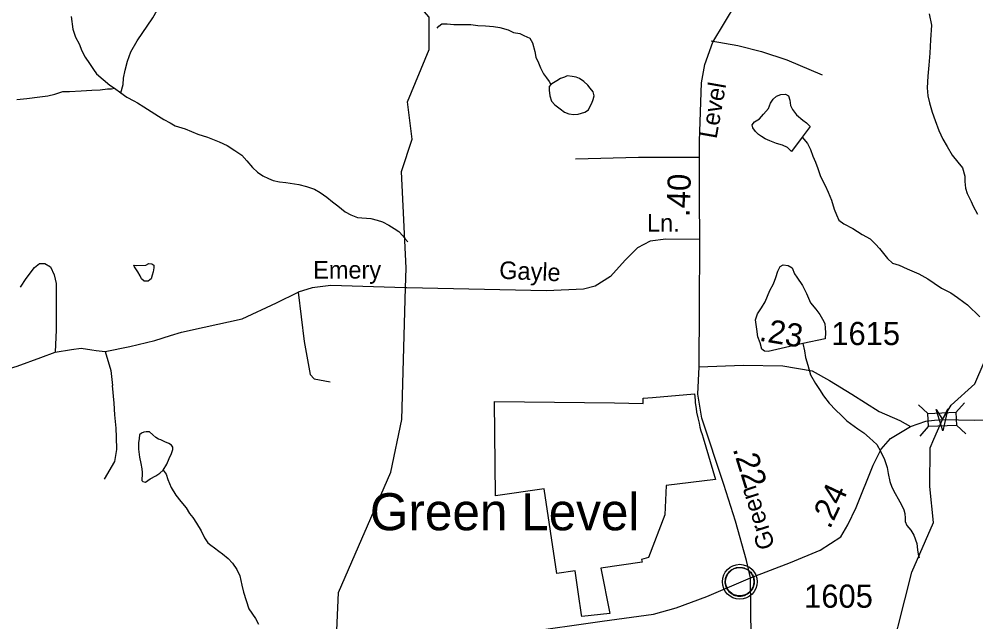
# Model space of a CAD drawing. Extents: x 2001466 to 2224147, y 644118 to 847247.
# Drawn here: x 2024898 to 2030071, y 738177 to 741433 of the extents above; entities that cross this region are included whole.
import ezdxf

# ---------------------------------------------------------------- set-up
doc = ezdxf.new("R2010")
doc.units = 0
for name, color, linetype in [('Exist Boundary Political City Limit New', 7, 'Continuous'), ('Exist Civil Demographics Community CELL', 7, 'Continuous'), ('Exist Civil Demographics Community Label', 7, 'Continuous'), ('Exist Hydrographic Creek Single Shore', 7, 'Continuous'), ('Exist Hydrographic Misc Water Feature', 7, 'Continuous'), ('Exist Road Non-System Type 51', 7, 'Continuous'), ('Exist Road Non-System Type 51 Label', 7, 'Continuous'), ('Exist Road Secondary Mileage Hundredths English Label', 7, 'Continuous'), ('Exist Road Secondary Structure Standard Bridge Attributed CELL', 7, 'Continuous'), ('Exist Road Secondary Structure Standard Bridge CELL', 7, 'Continuous'), ('Exist Road Secondary Type 51 Attributed', 7, 'Continuous'), ('Exist Road Secondary Type 51 Label', 7, 'Continuous'), ('Exist Road Secondary Type 51 Number Label', 7, 'Continuous'), ('Map Preparation Boundary City Limit Buffer Line', 7, 'Continuous')]:
    doc.layers.add(name, color=color, linetype=linetype)

msp = doc.modelspace()

# ---------------------------------------------------------------- linework, layer by layer
at = {"layer": 'Exist Boundary Political City Limit New'}
msp.add_lwpolyline([(2028553.9, 739360.9), (2028557.9, 739330.2), (2028561, 739309.8), (2028566.9, 739279.4), (2028573.8, 739249.7), (2028578.8, 739229.8), (2028584.4, 739209.9), (2028590.5, 739190.2), (2028596.8, 739172.1), (2028663.5, 738946.8), (2028395.5, 738914.3), (2028389, 738754.8), (2028301.2, 738525.5), (2028263.5, 738513.7), (2028266.4, 738499.6), (2028043.5, 738468.2), (2028092.4, 738223.1), (2027940.5, 738205.8), (2027939.1, 738214.6), (2027922, 738327.6), (2027903.6, 738453), (2027805.6, 738438.4), (2027737.4, 738896.3), (2027472.8, 738857.9), (2027467.5, 739367.9), (2028117.5, 739360.3), (2028272, 739356.4), (2028271.6, 739385.7), (2028322.4, 739389.6), (2028550, 739409.6), (2028552.5, 739375.4), (2028553.9, 739360.9)], dxfattribs=at)
at = {"layer": 'Exist Civil Demographics Community CELL'}
msp.add_lwpolyline([(2028716.7, 738406.4), (2028717.7, 738411.9), (2028719.5, 738418.5), (2028722.4, 738425.7), (2028725.3, 738431.5), (2028728.7, 738437.2), (2028732.4, 738442.3), (2028736.4, 738446.7), (2028741, 738451.3), (2028746.5, 738455.9), (2028751.9, 738459.5), (2028756.8, 738462.4), (2028761.9, 738464.8), (2028767.3, 738467.1), (2028773, 738469), (2028777.3, 738470.1), (2028782.1, 738470.8), (2028786.3, 738471.6), (2028792.6, 738471.8), (2028797.1, 738471.7), (2028802.7, 738471.5), (2028807.6, 738470.7), (2028812.5, 738469.8), (2028817.5, 738468.3), (2028822.7, 738466.4), (2028829.4, 738463.5), (2028835.6, 738460), (2028840.7, 738456.4), (2028845.9, 738452.4), (2028849.2, 738449.3), (2028853.3, 738444.9), (2028857.2, 738440.2), (2028860.2, 738435.6), (2028863.4, 738430.6), (2028865.8, 738425.5), (2028867.8, 738420.4), (2028869.4, 738415.4), (2028870.7, 738410.8), (2028871.8, 738404.8), (2028872.4, 738400.1), (2028872.7, 738394.1), (2028872.5, 738388.3), (2028871.9, 738382.6), (2028871, 738377.1), (2028869.3, 738371), (2028867.5, 738365.1), (2028865.2, 738360.1), (2028862, 738354.1), (2028858.7, 738348.7), (2028855.3, 738344.1), (2028851, 738339.3), (2028845.8, 738334.3), (2028840.7, 738330.2), (2028835.7, 738326.8), (2028831.4, 738324.3), (2028824.6, 738321), (2028817.4, 738318.3), (2028811.5, 738316.9), (2028804.9, 738315.6), (2028800.5, 738315.1), (2028796, 738314.8), (2028790.4, 738314.8), (2028786.1, 738315.2), (2028780.5, 738316), (2028774.6, 738317.3), (2028770, 738318.6), (2028764.8, 738320.5), (2028760.2, 738322.4), (2028756.3, 738324.7), (2028749.5, 738328.8), (2028743.9, 738333), (2028739, 738337.5), (2028734.5, 738342.4), (2028731.4, 738346.3), (2028728.4, 738350.5), (2028724.3, 738357.6), (2028722.6, 738361.2), (2028720.8, 738365.2), (2028718.3, 738373.4), (2028716.7, 738380.4), (2028716, 738385.6), (2028715.7, 738391.9), (2028715.6, 738396.6), (2028716.2, 738403.1)], close=True, dxfattribs=at)
for centre, radius in [((2028794.3, 738393.9), 94.3), ((2028794.1, 738394.2), 76.7)]:
    msp.add_circle(centre, radius, dxfattribs=at)
at = {"layer": 'Exist Hydrographic Creek Single Shore'}
for points in [[(2026987.2, 739982.2), (2026990.3, 740087.1), (2026965.3, 740609.4), (2027023.3, 740785.4), (2026998.3, 740986), (2027114.3, 741269.1), (2027114.3, 741443), (2027048.3, 741519.8), (2027048.3, 741647.4)], [(2026442.4, 736836.9), (2026442.4, 736951.8), (2026525.2, 737153.5), (2026567.3, 737359.4), (2026575.3, 737634.8), (2026600.3, 737762.3), (2026625.3, 738336), (2026908.3, 738986.4), (2026966.3, 739270.6), (2026987.2, 739982.2)], [(2029041.2, 737319.5), (2029076.3, 737355.3), (2029333.2, 737512.9), (2029575.4, 737855.7), (2029724.2, 738446.5), (2029841.3, 738713.3), (2029821.2, 738907.8), (2029822.7, 739116.8), (2029843.6, 739163.8), (2029889.8, 739269.7), (2029936.8, 739347.3), (2030065.2, 739463.3), (2030165.3, 739697.5)]]:
    msp.add_lwpolyline(points, dxfattribs=at)
at = {"layer": 'Exist Hydrographic Misc Water Feature'}
msp.add_line((2025413, 741059.4), (2025448.9, 741034.9), dxfattribs=at)
for points in [[(2025448.9, 741034.9), (2025459.8, 741079.7), (2025463.3, 741114.2), (2025471.1, 741157.5), (2025484.8, 741205.6), (2025502.4, 741256.1), (2025535.9, 741316.1), (2025567.4, 741360.5), (2025591.2, 741394.5), (2025621.2, 741440.7), (2025644.5, 741481.1), (2025664.4, 741516.8), (2025678.4, 741537.1), (2025695.6, 741563.8)], [(2025178.9, 741448), (2025189.3, 741378.1), (2025203.5, 741336), (2025221.9, 741300.3), (2025236.3, 741262.4), (2025254.5, 741226.7), (2025278.5, 741192.5), (2025300.9, 741160.9), (2025317.3, 741136.8), (2025389.4, 741077.1), (2025413, 741059.4)], [(2029818, 741461.6), (2029830.5, 741399.8), (2029824.9, 741322), (2029821.6, 741249.9), (2029816.1, 741183.6), (2029810.6, 741125.4), (2029806.9, 741061.6), (2029811.2, 741018), (2029819.6, 740980.1), (2029833.7, 740929.7), (2029849.9, 740885.9), (2029870.4, 740832.2), (2029892.8, 740784.2), (2029915.4, 740744.3), (2029941.6, 740698.7), (2029974, 740661.1), (2029998, 740629.4), (2030010.5, 740584.9), (2030010.7, 740555.3), (2030014.8, 740519.2), (2030023.2, 740491.1), (2030045.4, 740447.2), (2030055.8, 740423.2), (2030079.8, 740379.3)], [(2027158, 741384.1), (2027167.2, 741395.1), (2027183.2, 741407.1), (2027213, 741407.3), (2027249.1, 741403.3), (2027275.1, 741403.6), (2027313, 741403.6), (2027341.1, 741403.9), (2027377.2, 741398.3), (2027419.5, 741396.6), (2027463.1, 741394), (2027497.4, 741388.4), (2027541.3, 741374.4), (2027571.4, 741360.6), (2027605.4, 741355), (2027627.6, 741344.7), (2027659.6, 741329.3), (2027673.7, 741305.3), (2027685.8, 741257.4), (2027692, 741226.9), (2027706.1, 741197.2), (2027716.2, 741169), (2027732.4, 741137.5), (2027748.6, 741115.1), (2027764.6, 741095.9), (2027773.4, 741080.1)], [(2027773.4, 741080.1), (2027764.6, 741069.7), (2027764.6, 741049.9), (2027766.8, 741019.5), (2027776.9, 740989.7), (2027795.1, 740969.7), (2027823, 740947.8), (2027847.2, 740930.1), (2027869.3, 740922.3), (2027897.2, 740917.6), (2027921, 740920.4), (2027957.1, 740930.3), (2027977.2, 740942.2), (2027985.2, 740962.6), (2027995, 740978.8), (2028000.8, 740998.3), (2028006.7, 741018.7), (2028001, 741040.2), (2027984.6, 741060.2), (2027972.7, 741076), (2027950.5, 741096.2), (2027928.6, 741112.2), (2027910.4, 741119.9), (2027888.4, 741123.7), (2027860.5, 741125.9), (2027846.4, 741119.6), (2027824.2, 741111.9), (2027804.5, 741100), (2027786.5, 741088), (2027773.4, 741080.1)], [(2024886, 740999.6), (2024940, 741004.2), (2025009.9, 741012.7), (2025054, 741019.2), (2025091.9, 741027.4), (2025133.7, 741041.3), (2025169.6, 741041.4), (2025233.8, 741045.8), (2025291.8, 741048.7), (2025335.7, 741051.1), (2025375.7, 741056.8), (2025397.6, 741057.2), (2025413, 741059.4)], [(2025448.9, 741034.9), (2025479.9, 741012.1), (2025518.2, 740992.4), (2025538.5, 740980.5), (2025572.6, 740958.5), (2025650.9, 740909.4), (2025681, 740891.5), (2025715.3, 740873.5), (2025741.5, 740857.4), (2025795.2, 740839.9), (2025863.7, 740812.3), (2025915.8, 740794.8), (2025980.2, 740769.7), (2026022.2, 740750), (2026064.3, 740723.7), (2026102.6, 740698.3), (2026128.9, 740668.2), (2026159, 740632.3), (2026187.1, 740607.2), (2026215.6, 740586.9), (2026245.5, 740571.5), (2026271.6, 740561.2), (2026305.6, 740553.9), (2026339.7, 740549.9), (2026409.8, 740540.3), (2026452, 740528.8), (2026494.3, 740514.8), (2026526.3, 740497), (2026562.3, 740471.6), (2026592.5, 740445.5), (2026620.6, 740423.6), (2026660.8, 740392.4), (2026691.1, 740376.2), (2026727.2, 740360.7), (2026799.4, 740355.2), (2026833.4, 740347.1), (2026863.4, 740337.4), (2026897.6, 740319.5), (2026925.9, 740301.7), (2026951.7, 740286.4), (2026971.8, 740262.3), (2026984.1, 740248.1), (2027000.3, 740229.7)], [(2029132.3, 740794.8), (2029074.4, 740717.2), (2029052.3, 740739), (2029026, 740752.7), (2028992, 740760.7), (2028956.1, 740776.2), (2028932.1, 740786.6), (2028911.8, 740798.5), (2028895.8, 740810.3), (2028879.8, 740826.2), (2028865.7, 740846.2), (2028861.6, 740861.8), (2028873.7, 740878), (2028901.6, 740894.6), (2028923.3, 740920.5), (2028949.4, 740950.3), (2028961.2, 740978.7), (2028975, 741000.6), (2028993.2, 741016.7), (2029017, 741025.2), (2029041, 741027.2), (2029057.2, 741018.6), (2029065.2, 740994.7), (2029069.1, 740966.7), (2029079.2, 740945.1), (2029101.5, 740916.8), (2029135.3, 740887.4), (2029155.6, 740873), (2029175.5, 740853.8), (2029132.3, 740794.8)], [(2029132.3, 740794.8), (2029161, 740761.4), (2029177.2, 740729), (2029189.3, 740693.5), (2029203.6, 740659.6), (2029215.7, 740625.7), (2029230.1, 740583.6), (2029256.5, 740533.9), (2029272.9, 740498.2), (2029291, 740454.4), (2029305.3, 740406.5), (2029317.8, 740376.7), (2029329.9, 740346.2), (2029356.2, 740326.7), (2029406.2, 740302.8), (2029456.4, 740268.9), (2029498.9, 740245.9), (2029528.8, 740217.4), (2029549.3, 740194), (2029571.5, 740166.5), (2029593.6, 740140.6), (2029619.9, 740114.7), (2029655.8, 740104.9), (2029700, 740085.1), (2029762.2, 740057.6), (2029810.4, 740029.5), (2029844.6, 740005.9), (2029884.6, 739980.5), (2029935, 739954.8), (2029971.1, 739928.7), (2030005.4, 739905), (2030025.5, 739889), (2030091.9, 739825.3)], [(2025595.1, 740018.1), (2025590.4, 740018.1), (2025574.4, 740017.6), (2025560.3, 740030.3), (2025552.1, 740046), (2025540.4, 740067.5), (2025521.9, 740095.8), (2025518, 740104.1), (2025532.2, 740102.2), (2025584, 740104.4), (2025600, 740112.2), (2025616, 740111.9), (2025626.1, 740104.4), (2025626.1, 740090.3), (2025622, 740068.3), (2025618.3, 740050.3), (2025612.3, 740030), (2025604.3, 740024.4), (2025595.1, 740018.1)], [(2029134.9, 739680), (2028948.3, 739637.8), (2028928.4, 739639.9), (2028914.3, 739650), (2028904.4, 739683.9), (2028891.9, 739716.1), (2028886, 739758), (2028879.8, 739808.2), (2028889.7, 739841.7), (2028911.6, 739874.1), (2028931.5, 739906.4), (2028956.9, 739966.6), (2028976.8, 740003.9), (2028988.9, 740036.5), (2029000.8, 740072.3), (2029012.7, 740096.7), (2029028.7, 740106.2), (2029056.6, 740102.3), (2029076.7, 740088.8), (2029090.8, 740056.5), (2029102.9, 740039.1), (2029133.1, 739995), (2029155.2, 739951.1), (2029177.4, 739901.4), (2029205.7, 739865.5), (2029227.8, 739837.2), (2029242, 739813.2), (2029253.9, 739789.1), (2029256.1, 739763.6), (2029258.2, 739739.8), (2029256.3, 739707), (2029134.9, 739680)], [(2029134.9, 739680), (2029145, 739641.2), (2029149.1, 739605), (2029161.6, 739563), (2029175.9, 739511), (2029204.4, 739465.3), (2029224.7, 739432.1), (2029246.9, 739398), (2029277, 739358), (2029313.3, 739320.4), (2029341.6, 739294.4), (2029373.8, 739262.5), (2029432.3, 739219.5), (2029464.4, 739197.5), (2029496.4, 739171.4), (2029534.8, 739136.2), (2029555.1, 739099.7), (2029577.4, 739054.1), (2029591.8, 739012), (2029596.1, 738978.2), (2029606.3, 738936.2), (2029616.6, 738904.8), (2029634.8, 738870.8), (2029651, 738841), (2029669.1, 738808.6), (2029681.6, 738782.9), (2029685.7, 738763.2), (2029688, 738736.9), (2029688, 738718.8), (2029698.2, 738697.3), (2029718.5, 738673.1), (2029734.5, 738644.9), (2029750.7, 738601), (2029755.2, 738567.3), (2029759.3, 738543.4), (2029764, 738523.7)], [(2025676.9, 738996.7), (2025696.2, 739028.4), (2025710.1, 739060), (2025721.8, 739086), (2025729.8, 739108), (2025730, 739120.4), (2025721.8, 739132), (2025707.7, 739140.5), (2025685.7, 739149.9), (2025663.8, 739160.2), (2025651.7, 739163.8), (2025637.8, 739173.9), (2025621.8, 739188.2), (2025603.7, 739204.1), (2025585.5, 739203.7), (2025571.5, 739201.5), (2025559.6, 739196), (2025549.8, 739187.2), (2025547.7, 739167.5), (2025543.6, 739143.8), (2025543.8, 739109.4), (2025548.2, 739067.4), (2025556.2, 739033.6), (2025562.1, 739003.1), (2025562.5, 738983.5), (2025562.7, 738965.4), (2025560.7, 738953.2), (2025561.9, 738941.7), (2025566.8, 738935.8), (2025580.8, 738931.4), (2025606.6, 738949.8), (2025636.5, 738965.6), (2025658.5, 738979.9), (2025676.9, 738996.7)], [(2025676.9, 738996.7), (2025692.5, 738975.9), (2025702.6, 738946.2), (2025721, 738902.3), (2025745, 738862.5), (2025773.1, 738826.6), (2025801, 738792.4), (2025819.2, 738762.5), (2025837.3, 738740.8), (2025857.4, 738710.8), (2025881.6, 738668.6), (2025900, 738631.2), (2025918.1, 738604.6), (2025933.9, 738591.2), (2025954.2, 738576.8), (2025978.1, 738559.1), (2025998.2, 738545.6), (2026028.4, 738519.5), (2026052.4, 738493.6), (2026074.7, 738459.6), (2026090.7, 738425.6), (2026102.8, 738375.3), (2026111, 738337.4), (2026125.4, 738293.6), (2026139.5, 738247.4), (2026175.6, 738195.8), (2026191.8, 738164.3)]]:
    msp.add_lwpolyline(points, dxfattribs=at)
at = {"layer": 'Exist Road Non-System Type 51'}
for points in [[(2028638.9, 741315.5), (2028783.6, 741289.8), (2028911.5, 741257.5), (2029049.4, 741213.1), (2029239.4, 741131.8)], [(2028576.5, 740685.8), (2028246.1, 740685.8), (2027906.5, 740676.8)], [(2028577.9, 740242.7), (2028394.5, 740244.7), (2028309, 740233.4), (2028241, 740198), (2028173.9, 740130.8), (2028095.8, 740042.1), (2028012.6, 739990.4), (2027950.1, 739974.6), (2027750, 739965.6), (2026994.5, 739982.2), (2026987.2, 739982.2)], [(2024905.4, 739985.6), (2024935.5, 740031.6), (2024981.7, 740091.5), (2025007.8, 740113.3), (2025037.8, 740113.3), (2025067.6, 740095.1), (2025087.5, 740051.1), (2025098.9, 740004.8), (2025098.9, 739946.3), (2025098.9, 739867.5), (2025098.9, 739755), (2025092.1, 739633.4)], [(2026987.2, 739982.2), (2026583.6, 739994.9), (2026482.4, 739981.4), (2026406, 739958.9)], [(2025363.8, 739637.9), (2025496.5, 739664.9), (2025631.4, 739696.5), (2025716.9, 739723.5), (2025775.3, 739741.5), (2025899, 739769.8), (2026104.6, 739814.8), (2026289, 739900.3), (2026406, 739958.9)], [(2026406, 739958.9), (2026438.8, 739692), (2026472.5, 739514.2), (2026492.8, 739489.4), (2026580.5, 739473.7)], [(2024676, 739500.7), (2024754.8, 739518.7), (2024888.4, 739557.9), (2025016.4, 739605.5), (2025092.1, 739633.4)], [(2025092.1, 739633.4), (2025180.5, 739649), (2025234.4, 739654.9), (2025290.5, 739646.7), (2025314.3, 739642.4), (2025363.8, 739637.9)], [(2025363.8, 739637.9), (2025393.5, 739534.4), (2025402.5, 739453.4)], [(2025359.7, 738948.4), (2025416, 739043.8), (2025427.2, 739109.1), (2025425, 739174.3), (2025422.7, 739223.8), (2025416, 739295.9), (2025411.5, 739358.9), (2025402.5, 739453.4)]]:
    msp.add_lwpolyline(points, dxfattribs=at)
at = {"layer": 'Exist Road Secondary Structure Standard Bridge Attributed CELL'}
msp.add_lwpolyline([(2029918.9, 739327.8), (2029892.4, 739208.8), (2029855.9, 739325.1), (2029889.8, 739269.7)], close=True, dxfattribs=at)
at = {"layer": 'Exist Road Secondary Structure Standard Bridge CELL'}
for p, q in [((2029760.9, 739348.8), (2029811.8, 739302.3)), ((2029962.8, 739308.9), (2030009.3, 739359.8)), ((2029768.6, 739180.8), (2029815.1, 739231.8)), ((2029966, 739240), (2030016.9, 739193.5))]:
    msp.add_line(p, q, dxfattribs=at)
msp.add_lwpolyline([(2029811.8, 739302.3), (2029962.8, 739309.2), (2029966, 739238.7), (2029815.1, 739231.8)], close=True, dxfattribs=at)
at = {"layer": 'Exist Road Secondary Type 51 Attributed'}
for points in [[(2028574, 739554.6), (2028576.9, 739877.5), (2028578.1, 740226.1), (2028575.7, 740480.5), (2028576.9, 740774.4), (2028586.5, 741088.4), (2028605.4, 741187.4), (2028648.1, 741309), (2028774.8, 741516.7), (2028814.2, 741585.1)], [(2028852.4, 738415), (2028830.7, 738509.6), (2028771.2, 738720.5), (2028708.4, 738918.6), (2028588.5, 739277.7), (2028567.6, 739406.5), (2028574, 739554.6)], [(2028574, 739554.6), (2028811.8, 739563.5), (2029027, 739559.5), (2029184.7, 739533.7), (2029279.6, 739480.6), (2029400.3, 739408.1), (2029548.3, 739313.1), (2029659.4, 739264.8), (2029718, 739232.9)], [(2029718, 739232.9), (2029800.1, 739261.1), (2029846.6, 739266.7), (2029889.8, 739269.7)], [(2029889.8, 739269.7), (2030062.4, 739266.8), (2030538.7, 739275.6)], [(2028852.4, 738415), (2029068.8, 738497.1), (2029229.7, 738564.7), (2029340.7, 738637.2), (2029377.7, 738701.6), (2029422.8, 738795), (2029514.9, 739023.6), (2029558.3, 739109.8), (2029609.8, 739167.7), (2029718, 739232.9)], [(2023978.9, 737064.8), (2024314.8, 737199.3), (2024583.5, 737316), (2024905.3, 737445.6), (2025190.1, 737548.7), (2025556.6, 737660.6), (2026021.6, 737790.2), (2026256.5, 737841.7), (2026625.4, 737919), (2027071.9, 738022.9), (2027358.3, 738080.8), (2027620.2, 738120.3), (2028050.6, 738181.5), (2028327.4, 738218.5), (2028450.9, 738253.1), (2028616.6, 738314.3), (2028852.4, 738415)], [(2028880.9, 737330.7), (2028872, 737469.5), (2028872.1, 737584.9), (2028856, 738088.9), (2028852.4, 738415)]]:
    msp.add_lwpolyline(points, dxfattribs=at)
at = {"layer": 'Map Preparation Boundary City Limit Buffer Line'}
msp.add_lwpolyline([(2028553.9, 739360.9), (2028557.9, 739330.2), (2028561, 739309.8), (2028566.9, 739279.4), (2028573.8, 739249.7), (2028578.8, 739229.8), (2028584.4, 739209.9), (2028590.5, 739190.2), (2028596.8, 739172.1), (2028663.5, 738946.8), (2028395.5, 738914.3), (2028389, 738754.8), (2028301.2, 738525.5), (2028263.5, 738513.7), (2028266.4, 738499.6), (2028043.5, 738468.2), (2028092.4, 738223.1), (2027940.5, 738205.8), (2027939.1, 738214.6), (2027922, 738327.6), (2027903.6, 738453), (2027805.6, 738438.4), (2027737.4, 738896.3), (2027472.8, 738857.9), (2027467.5, 739367.9), (2028117.5, 739360.3), (2028272, 739356.4), (2028271.6, 739385.7), (2028322.4, 739389.6), (2028550, 739409.6), (2028552.5, 739375.4), (2028553.9, 739360.9)], dxfattribs=at)

# ---------------------------------------------------------------- texts
at = {"layer": 'Exist Civil Demographics Community Label'}
msp.add_text('Green Level', height=200, dxfattribs=at).set_placement((2026794.8, 738672.2))
at = {"layer": 'Exist Road Non-System Type 51 Label'}
for s, p in [('Ln.', (2028292.7, 740284.7)), ('Emery', (2026488.1, 740031.4))]:
    msp.add_text(s, height=95, dxfattribs=at).set_placement(p)
msp.add_text('Gayle', height=95, rotation=357.494, dxfattribs=at).set_placement((2027492.1, 740031.1))
at = {"layer": 'Exist Road Secondary Mileage Hundredths English Label'}
for s, rotation, p in [('.40', 88.0908, (2028522.7, 740363.4)), ('.23', 350.5346, (2028894.7, 739696.5)), ('.22', 287.4415, (2028755.1, 739111.4)), ('.24', 64.662, (2029281.1, 738674.6))]:
    msp.add_text(s, height=125, rotation=rotation, dxfattribs=at).set_placement(p)
at = {"layer": 'Exist Road Secondary Type 51 Label'}
for s, rotation, p in [('Level', 80.0047, (2028668.5, 740783.2)), ('Green', 107.7097, (2028985.8, 738585.2))]:
    msp.add_text(s, height=95, rotation=rotation, dxfattribs=at).set_placement(p)
at = {"layer": 'Exist Road Secondary Type 51 Number Label'}
for s, p in [('1615', (2029289.1, 739672.5)), ('1605', (2029142, 738253.7))]:
    msp.add_text(s, height=125, dxfattribs=at).set_placement(p)

doc.saveas('drawing.dxf')
